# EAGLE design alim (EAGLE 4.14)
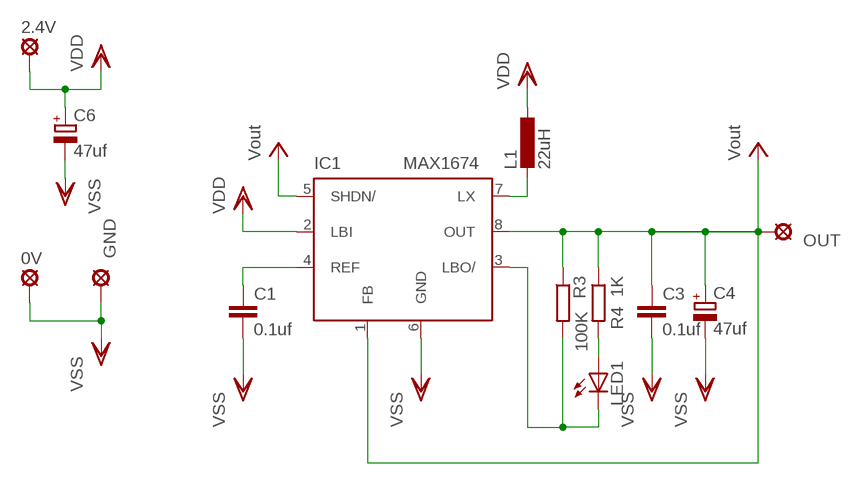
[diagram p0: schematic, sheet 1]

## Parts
0V  SE14  [SE14]
2.4V  SE14  [SE14]
C1  0.1uf  C-EUC0805  [C0805]
C3  0.1uf  C-EUC0805  [C0805]
C4  47uf  CPOL-EU153CLV-0810  [153CLV-0810]
C6  47uf  CPOL-EU153CLV-0810  [153CLV-0810]
GND  SE14  [SE14]
IC1  MAX1674  [UMAX8]
L1  22uH  L-EUL1812  [L1812]
LED1  LEDCHIP-LED0805  [CHIP-LED0805]
OUT  SE14  [SE14]
R3  100K  R-EU_M0805  [M0805]
R4  1K  R-EU_M0805  [M0805]

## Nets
N$1: C1.1 IC1.4(REF)
N$4: IC1.7(LX) L1.2
N$6: IC1.3(LBO/) LED1.C R3.2
N$7: LED1.A R4.2
VCC: C3.1 C4.+ IC1.1(FB) IC1.5(SHDN/) IC1.8(OUT) OUT.MP R3.1 R4.1 ; supply symbol labelled Vout
VDD: 2.4V.MP C6.+ IC1.2(LBI) L1.1
VSS: 0V.MP C1.2 C3.2 C4.- C6.- GND.MP IC1.6(GND)

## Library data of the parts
0V 2.4V GND OUT = solpad:SE14: SOLDER PAD
C1 C3 = rcl:C-EU: CAPACITOR, European symbol
C4 C6 = rcl:CPOL-EU: POLARIZED CAPACITOR, European symbol
IC1 = maxim:MAX1674: DC/DC CONVERTER
L1 = rcl:L-EU: INDUCTOR, European symbol
LED1 = led:LED: LED
R3 R4 = rcl:R-EU_: RESISTOR, European symbol

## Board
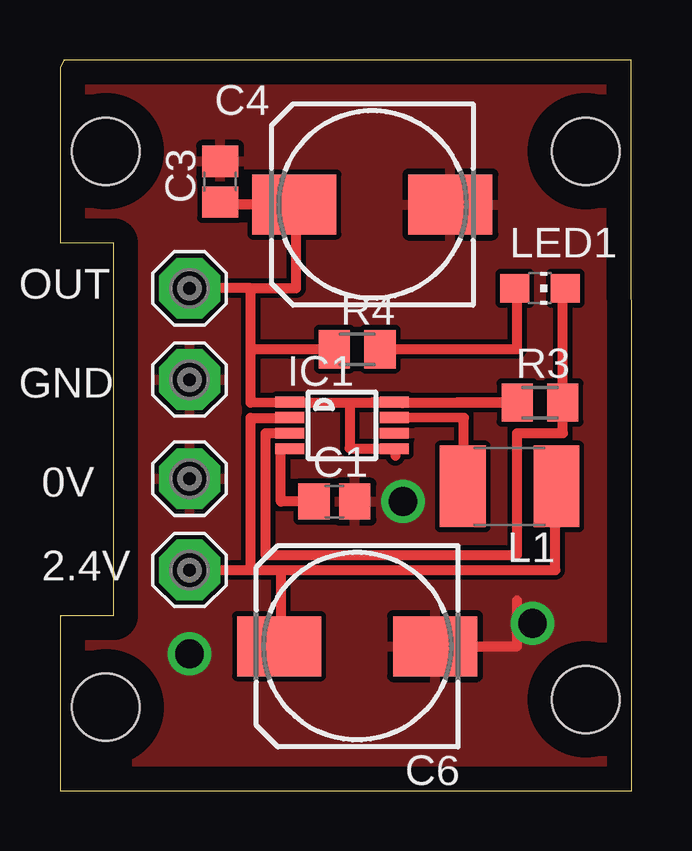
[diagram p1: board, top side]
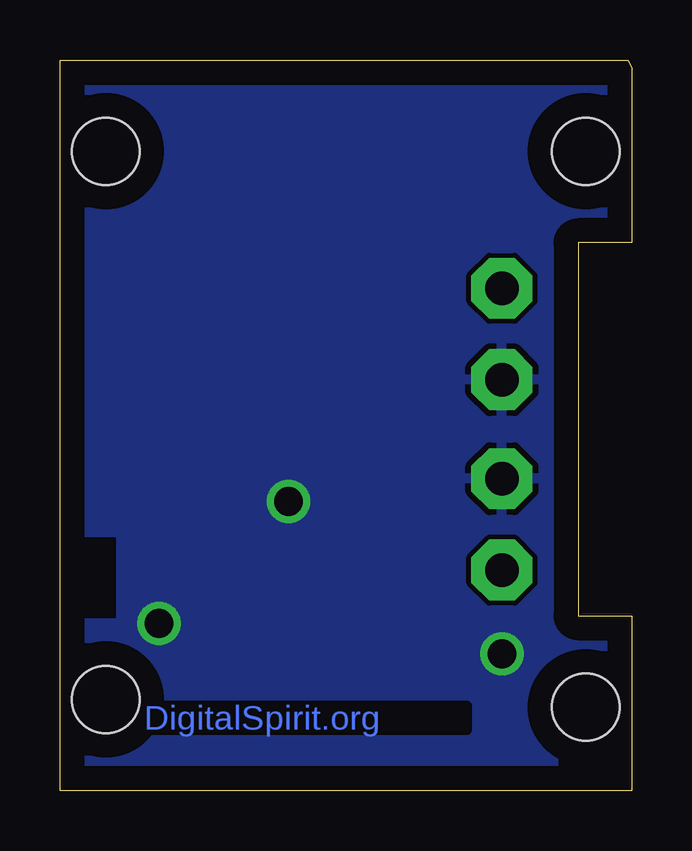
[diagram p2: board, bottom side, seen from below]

Size 23.81 x 30.47 mm. Coordinates in mm from the lower left corner, seen from the top.
Outline: 23.81,0 23.81,10.47 23.81,30.47 0.17,30.47 0,30.16 0,22.86 2.22,22.86 2.22,7.3 0,7.3 0,0 23.81,0
Copper layers (1*16): Top 0.035mm / dielectric 1.5mm / Bottom 0.035mm
Design rules "default": minimum track width 10mil, minimum drill 24mil, track to track 8mil, track to pad 8mil, pad to pad 8mil, via to via 8mil, smd to smd 8mil, copper to edge 40mil, drill to drill 8mil, minimum pad ring 10mil, minimum via ring 8mil, stop-mask expansion 4mil, vias tented up to drill 0mil, thermal gap 10mil
Holes 2.8 mm at 1.91,3.49 21.91,3.8 21.91,26.66 1.91,26.66

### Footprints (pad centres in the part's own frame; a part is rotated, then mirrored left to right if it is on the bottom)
SE14 = drill 1.397 pad 2.54 octagon: MP 0,0
C0805 = smd 1.3 x 1.5: 1 -0.85,0; 2 0.85,0
153CLV-0810 = smd 3.5 x 2.5: + 3.25,0; - -3.25,0
UMAX8 = smd 0.45 x 1.2: 1 -0.975,-2.175; 2 -0.325,-2.175; 3 0.325,-2.175; 4 0.975,-2.175; 5 0.975,2.175; 6 0.325,2.175; 7 -0.325,2.175; 8 -0.975,2.175
L1812 = smd 1.9 x 3.4: 1 -1.95,0; 2 1.95,0
CHIP-LED0805 = smd 1.2 x 1.2: A 0,-1.05; C 0,1.05
M0805 = smd 1.3 x 1.6: 1 -0.95,0; 2 0.95,0

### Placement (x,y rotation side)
0V  5.4,13.01 0 top
2.4V  5.4,9.2 0 top
C1  11.43,12.06 0 top
C3  6.67,25.39 90 top
C4  13.02,24.44 180 top
C6  12.38,6.03 180 top
GND  5.4,17.14 0 top
IC1  11.75,15.24 270 top
L1  18.73,12.7 180 top
LED1  20,20.95 270 top
OUT  5.4,20.95 0 top
R3  20,16.19 0 top
R4  12.38,18.41 0 top

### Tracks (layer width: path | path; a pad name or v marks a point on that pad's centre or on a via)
N$1
  Top 0.406: IC1.4 9.21,14.26 9.21,12.06 C1.1
N$4
  Top 0.406: 13.96,15.56 13.97,15.55 | 13.96,15.56 IC1.7 | 13.96,15.56 16.83,15.55 16.83,13.33 L1.2
N$6
  Top 0.406: IC1.3 8.57,14.92 8.57,9.84 19.05,9.84 19.05,14.92 20.96,14.92 20.96,16.82 | 20.96,16.82 R3.2 | LED1.C 20.96,20.95 20.96,16.82
N$7
  Top 0.406: R4.2 19.05,18.41 19.05,20.95 LED1.A
VCC
  Top 0.406: 7.94,18.41 7.94,16.19 9.84,16.21 IC1.1 9.84,16.19 12.06,16.19 | 5.08,20.95 OUT.MP 7.94,20.95 | 7.94,20.95 9.84,20.95 9.84,24.44 C4.+ 6.67,24.44 C3.1 | 13.97,13.97 IC1.5 13.95,14.26 13.97,14.28 12.06,14.28 12.06,16.19 | 13.65,16.19 13.02,16.19 13.67,16.21 IC1.8 14.27,16.16 | 12.06,16.19 14.27,16.16 | 7.94,18.41 7.94,20.95 | 7.94,18.41 R4.1 | 14.27,16.16 16.83,16.19 | 16.83,16.19 16.51,16.19 | R3.1 16.83,16.19 | R3.1 | 12.06,16.19 R3.1
VDD
  Top 0.406: 2.4V.MP 7.94,9.2 | C6.+ 9.21,6.03 9.21,9.2 | 7.94,9.2 9.21,9.2 | 7.94,9.2 7.94,15.55 9.53,15.55 9.53,15.56 IC1.2 | 9.21,9.2 20.64,9.2 20.64,13.33 L1.1
VSS  (via drill 1.2)
  Top 0.406: 19.05,7.93 19.05,7.3 19.05,6.03 C6.-
  other vias: 14.29,12.06 19.69,6.98 5.4,5.71
  pour Top: 0.32,30.16 23.5,30.16 23.5,10.79 23.5,6.98 23.5,0.31 0.32,0.31 0.32,6.98 2.54,6.98 2.54,23.17 0.32,23.17
  pour Bottom: 0.32,30.16 23.5,30.16 23.5,10.79 21.27,10.79 21.27,6.98 23.5,6.98 23.5,0.31 0.32,0.31 0.32,6.98 2.54,6.98 2.54,23.17 0.32,23.17

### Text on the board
Bottom: DigitalSpirit.org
